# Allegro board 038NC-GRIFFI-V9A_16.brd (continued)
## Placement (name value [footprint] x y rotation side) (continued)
UNK9SH38  SHORT  [DEFAULT_SHORT_SMALL]  120.18 484.64 0 top
UNK9SH39  SHORT  [DEFAULT_SHORT_SMALL]  122.38 484.64 0 top
UNK9SH40  SHORT  [DEFAULT_SHORT_SMALL]  124.58 484.64 0 top
UNK9SH41  SHORT  [DEFAULT_SHORT_SMALL]  126.79 484.64 0 top
UNK9TP_AVSS2/TST  TP01  [TP_040_T]  133.84 274.45 0 top
UNK9TP_GPIO0  TP01  [TP_040_T]  136.57 295.94 90 top
UNK9TP_GPIO1  TP01  [TP_040_T]  136.57 298.48 270 top
UNK9TP_GPIO2  TP01  [TP_040_T]  149.27 295.94 0 top
UNK9TP_GPIO3  TP01  [TP_040_T]  149.27 298.48 270 top
UNK9TP_GPIO4  TP01  [TP_040_T]  146.73 295.94 270 top
UNK9TP_LED0  TP01  [TP_040_T]  144.19 298.48 270 top
UNK9TP_LED1  TP01  [TP_040_T]  144.19 295.94 90 top
UNK9TP_LED2  TP01  [TP_040_T]  146.73 298.48 270 top
UNK9TP_LSIN1_F  TP01  [TP_040_T]  150.99 330.46 0 top
UNK9TP_LSIN1_G  TP01  [TP_040_T]  114.02 486.88 0 top
UNK9TP_LSIN1_S  TP01  [TP_040_T]  148.45 330.46 0 top
UNK9TP_LSIN2/NCHGEN_F  TP01  [TP_040_T]  150.99 335.54 0 top
UNK9TP_LSIN2/NCHGEN_G  TP01  [TP_040_T]  116 486.88 0 top
UNK9TP_LSIN2/NCHGEN_S  TP01  [TP_040_T]  148.45 335.54 0 top
UNK9TP_LSOUT1_F  TP01  [TP_040_T]  139.67 244.47 180 top
UNK9TP_LSOUT1_G  TP01  [TP_040_T]  117.98 486.88 0 top
UNK9TP_LSOUT1_S  TP01  [TP_040_T]  141.65 298.48 270 top
UNK9TP_LSOUT2/SUSPEND1_G  TP01  [TP_040_T]  119.96 486.88 0 top
UNK9TP_LSOUT2/SUSPEND1_S  TP01  [TP_040_T]  141.65 295.94 0 top
UNK9TP_LSOUT2/SUSPEND_F  TP01  [TP_040_T]  158.86 244.47 180 top
UNK9TP_NCHG/ATB0_F  TP01  [TP_040_T]  143.93 292.54 0 top
UNK9TP_NCHG/ATB0_G  TP01  [TP_040_T]  143.93 288.14 0 top
UNK9TP_NCHG/ATB0_S  TP01  [TP_040_T]  147.13 290.34 0 top
UNK9TP_NPG/ATB1_F  TP01  [TP_040_T]  136.47 292.54 0 top
UNK9TP_NPG/ATB1_G  TP01  [TP_040_T]  136.47 288.14 0 top
UNK9TP_NPG/ATB1_S  TP01  [TP_040_T]  139.67 292.54 0 top
UNK9TP_NTC  TP01  [TP_040_T]  151.39 307.08 180 top
UNK9TP_REF_5V  TP01  [TP_040_T]  154.59 242.27 180 top
UNK9TP_SCL  TP01  [TP_040_T]  136.47 330.46 0 top
UNK9TP_SDA  TP01  [TP_040_T]  139.67 330.46 0 top
UNK9TP_SHPHLD_F  TP01  [TP_040_T]  139.11 298.48 270 top
UNK9TP_SHPHLD_S  TP01  [TP_040_T]  139.11 295.94 90 top
UNK9TP_SW_F  TP01  [TP_040_T]  156.07 330.46 0 top
UNK9TP_SW_S  TP01  [TP_040_T]  153.53 330.46 0 top
UNK9TP_VBAT_F  TP01  [TP_040_T]  162.06 287.14 0 top
UNK9TP_VBAT_S  TP01  [TP_040_T]  158.86 287.14 0 top
UNK9TP_VBUS_F  TP01  [TP_040_T]  143.37 330.46 0 top
UNK9TP_VBUS_S  TP01  [TP_040_T]  145.91 330.46 0 top
UNK9TP_VDDIO_F  TP01  [TP_040_T]  158.61 335.54 0 top
UNK9TP_VDDIO_S  TP01  [TP_040_T]  121.95 486.88 0 top
UNK9TP_VEST  TP01  [TP_040_T]  133.28 269.26 0 top
UNK9TP_VOUT_F  TP01  [TP_040_T]  123.93 486.88 0 top
UNK9TP_VOUT_S  TP01  [TP_040_T]  158.61 330.46 0 top
UNK9TP_VSYS_F  TP01  [TP_040_T]  145.91 335.54 0 top
UNK9TP_VSYS_S  TP01  [TP_040_T]  143.37 335.54 0 top
UNK9U1  ADR4550BRZ-SOIC8  [SO8_195X127MM]  156.83 296.98 180 bottom
UNK10C1  1U-6.3-X7R-S6-MU  [C0603]  139.36 142.49 90 bottom
UNK10C2  2.2U-25-X8R-SA-TDK  [C1206]  155.84 178.21 180 bottom
UNK10C3  10U-6.3-X7R-S6-SS  [C0603]  151.92 177.36 270 bottom
UNK10C4  2.2U-25-X8R-SA-TDK  [C1206]  148.38 192.05 180 bottom
UNK10C5  2.2U-25-X8R-SA-TDK  [C1206]  142.68 192.05 0 bottom
UNK10C6  4.7U-6.3-X-S6  [C0603]  161.21 178.21 180 bottom
UNK10C7  0.1U-25-X7R-S6-YA  [C0603]  161.75 238.65 0 bottom
UNK10C8  1U-50-X7R-S6-TY  [C0603]  161.75 237.13 0 bottom
UNK10C9  0.1U-25-X7R-S6-YA  [C0603]  151.9 237.3 270 bottom
UNK10C12  2.2U-25-X8R-SA-TDK  [C1206]  146.98 142.89 90 bottom
UNK10CS1  CNC-S4  [C0402]  142.12 211.3 180 bottom
UNK10CS4  CNC-S4  [C0402]  142.12 207.49 0 bottom
UNK10CS5  CNC-S4  [C0402]  142.12 206.22 0 bottom
UNK10CS19  CNC-S4  [C0402]  155.85 207.02 0 bottom
UNK10CS20  CNC-S4  [C0402]  155.85 208.29 0 bottom
UNK10CS21  CNC-S4  [C0402]  155.85 209.56 0 bottom
UNK10CS22  CNC-S4  [C0402]  153.2 213.05 90 bottom
UNK10CS23  CNC-S4  [C0402]  151.93 213.05 90 bottom
UNK10CS25  CNC-S4  [C0402]  148.12 213.05 90 bottom
UNK10CS26  CNC-S4  [C0402]  146.85 213.05 270 bottom
UNK10CS27  CNC-S4  [C0402]  145.58 213.05 270 bottom
UNK10CS28  CNC-S4  [C0402]  144.31 213.05 90 bottom
UNK10K1  UA2-12NJ-V2  [RL_NECUA2_12V_V2]  152.99 185.33 90 bottom
UNK10K2  UA2-12NJ-V2  [RL_NECUA2_12V_V2]  145.53 185.33 90 bottom
UNK10K3  UA2-12NJ-V2  [RL_NECUA2_12V_V2]  136.66 207.46 270 bottom
UNK10K4  UA2-12NJ-V2  [RL_NECUA2_12V_V2]  145.53 169.7 90 bottom
UNK10K5  UA2-12NJ-V2  [RL_NECUA2_12V_V2]  138.07 169.7 90 bottom
UNK10K6  UA2-12NJ-V2  [RL_NECUA2_12V_V2]  152.99 169.3 270 bottom
UNK10K7  UA2-12NJ-V2  [RL_NECUA2_12V_V2]  160.46 169.7 90 bottom
UNK10K8  UA2-12NJ-V2  [RL_NECUA2_12V_V2]  138.07 185.33 90 bottom
UNK10K9  UA2-12NJ-V2  [RL_NECUA2_12V_V2]  160.46 142.72 270 bottom
UNK10K10  UA2-12NJ-V2  [RL_NECUA2_12V_V2]  160.46 185.33 90 bottom
UNK10K11  UA2-12NJ-V2  [RL_NECUA2_12V_V2]  152.99 229.98 90 bottom
UNK10K12  UA2-12NJ-V2  [RL_NECUA2_12V_V2]  160.46 229.98 90 bottom
UNK10K13  UA2-12NJ-V2  [RL_NECUA2_12V_V2]  138.07 229.58 270 bottom
UNK10K14  UA2-12NJ-V2  [RL_NECUA2_12V_V2]  145.53 229.58 270 bottom
UNK10R1  4.7K-1-S4-WA  [R0402]  136.51 201.49 180 bottom
UNK10R2  3.01K-0.1-S4-PAN  [R0402]  141.8 166.2 90 bottom
UNK10R3  10K-0.1-S4  [R0402]  149.26 172.8 270 bottom
UNK10R7  1K-1-S4  [R0402]  161.78 149.43 0 bottom
UNK10R8  1K-1-S4  [R0402]  159.14 149.43 180 bottom
UNK10R13  0-5-S4  [R0402]  133.39 484.56 0 top
UNK10R14  0-5-S4  [R0402]  135.6 484.56 0 top
UNK10R41  24K-0.1-S4  [R0402]  164.26 166.2 90 bottom
UNK10R42  44.2K-0.1-S4-PAN  [R0402]  164.26 168.4 90 bottom
UNK10RS1  0-5-S4  [R0402]  142.12 208.76 0 bottom
UNK10RS2  NC/0-5-S4  [R0402]  149.39 213.05 270 bottom
UNK10RS3  NC/0-5-S4  [R0402]  142.12 210.03 0 bottom
UNK10RS4  0-5-S4  [R0402]  150.66 213.05 270 bottom
UNK10RS5  0-5-S4  [R0402]  150.02 214.7 0 bottom
UNK10SH2  SHORT  [DEFAULT_SHORT_SMALL]  75.34 475.82 0 top
UNK10SH7  SHORT  [DEFAULT_SHORT_SMALL]  106.18 475.82 0 top
UNK10SH9  SHORT  [DEFAULT_SHORT_SMALL]  108.39 475.82 0 top
UNK10SH14  SHORT  [DEFAULT_SHORT_SMALL]  70.93 475.82 0 top
UNK10SH16  SHORT  [DEFAULT_SHORT_SMALL]  73.14 475.82 0 top
UNK10SH20  SHORT  [DEFAULT_SHORT_SMALL]  77.54 475.82 0 top
UNK10SH29  SHORT  [DEFAULT_SHORT_SMALL]  79.75 475.82 0 top
UNK10SH30  SHORT  [DEFAULT_SHORT_SMALL]  81.95 475.82 0 top
UNK10SH32  SHORT  [DEFAULT_SHORT_SMALL]  84.15 475.82 0 top
UNK10SH33  SHORT  [DEFAULT_SHORT_SMALL]  86.36 475.82 0 top
UNK10SH34  SHORT  [DEFAULT_SHORT_SMALL]  88.56 475.82 0 top
UNK10SH35  SHORT  [DEFAULT_SHORT_SMALL]  90.76 475.82 0 top
UNK10SH36  SHORT  [DEFAULT_SHORT_SMALL]  92.97 475.82 0 top
UNK10SH37  SHORT  [DEFAULT_SHORT_SMALL]  95.17 475.82 0 top
UNK10SH38  SHORT  [DEFAULT_SHORT_SMALL]  97.37 475.82 0 top
UNK10SH39  SHORT  [DEFAULT_SHORT_SMALL]  99.58 475.82 0 top
UNK10SH40  SHORT  [DEFAULT_SHORT_SMALL]  101.78 475.82 0 top
UNK10SH41  SHORT  [DEFAULT_SHORT_SMALL]  103.98 475.82 0 top
UNK10TP_AVSS2/TST  TP01  [TP_040_T]  133.84 214.45 0 top
UNK10TP_GPIO0  TP01  [TP_040_T]  149.17 178.59 270 top
UNK10TP_GPIO1  TP01  [TP_040_T]  149.17 176.05 90 top
UNK10TP_GPIO2  TP01  [TP_040_T]  136.47 178.59 180 top
UNK10TP_GPIO3  TP01  [TP_040_T]  136.47 176.05 90 top
UNK10TP_GPIO4  TP01  [TP_040_T]  139.01 178.59 90 top
UNK10TP_LED0  TP01  [TP_040_T]  141.55 176.05 90 top
UNK10TP_LED1  TP01  [TP_040_T]  141.55 178.59 270 top
UNK10TP_LED2  TP01  [TP_040_T]  139.01 176.05 90 top
UNK10TP_LSIN1_F  TP01  [TP_040_T]  146.98 146.72 180 top
UNK10TP_LSIN1_G  TP01  [TP_040_T]  197.79 484.9 0 top
UNK10TP_LSIN1_S  TP01  [TP_040_T]  149.52 146.72 180 top
UNK10TP_LSIN2/NCHGEN_F  TP01  [TP_040_T]  146.98 141.64 180 top
UNK10TP_LSIN2/NCHGEN_G  TP01  [TP_040_T]  199.77 484.9 0 top
UNK10TP_LSIN2/NCHGEN_S  TP01  [TP_040_T]  149.52 141.64 180 top
UNK10TP_LSOUT1_F  TP01  [TP_040_T]  201.75 484.9 0 top
UNK10TP_LSOUT1_G  TP01  [TP_040_T]  203.73 484.9 0 top
UNK10TP_LSOUT1_S  TP01  [TP_040_T]  144.09 176.05 90 top
UNK10TP_LSOUT2/SUSPEND1_G  TP01  [TP_040_T]  205.71 484.9 0 top
UNK10TP_LSOUT2/SUSPEND1_S  TP01  [TP_040_T]  144.09 178.59 180 top
UNK10TP_LSOUT2/SUSPEND_F  TP01  [TP_040_T]  207.69 484.9 0 top
UNK10TP_NCHG/ATB0_F  TP01  [TP_040_T]  143.93 233.58 0 top
UNK10TP_NCHG/ATB0_G  TP01  [TP_040_T]  143.93 229.18 0 top
UNK10TP_NCHG/ATB0_S  TP01  [TP_040_T]  147.13 231.38 0 top
UNK10TP_NPG/ATB1_F  TP01  [TP_040_T]  136.47 233.58 0 top
UNK10TP_NPG/ATB1_G  TP01  [TP_040_T]  136.47 229.18 0 top
UNK10TP_NPG/ATB1_S  TP01  [TP_040_T]  139.67 233.58 0 top
UNK10TP_NTC  TP01  [TP_040_T]  147.13 167.9 0 top
UNK10TP_REF_5V  TP01  [TP_040_T]  209.67 484.9 0 top
UNK10TP_SCL  TP01  [TP_040_T]  162.06 144.52 180 top
UNK10TP_SDA  TP01  [TP_040_T]  158.86 144.52 180 top
UNK10TP_SHPHLD_F  TP01  [TP_040_T]  146.63 176.05 90 top
UNK10TP_SHPHLD_S  TP01  [TP_040_T]  146.63 178.59 270 top
UNK10TP_SW_F  TP01  [TP_040_T]  141.9 146.72 180 top
UNK10TP_SW_S  TP01  [TP_040_T]  144.44 146.72 180 top
UNK10TP_VBAT_F  TP01  [TP_040_T]  162.06 228.18 0 top
UNK10TP_VBAT_S  TP01  [TP_040_T]  158.86 228.18 0 top
UNK10TP_VBUS_F  TP01  [TP_040_T]  154.6 146.72 180 top
UNK10TP_VBUS_S  TP01  [TP_040_T]  152.06 146.72 180 top
UNK10TP_VDDIO_F  TP01  [TP_040_T]  139.36 141.64 180 top
UNK10TP_VDDIO_S  TP01  [TP_040_T]  136.82 141.64 180 top
UNK10TP_VEST  TP01  [TP_040_T]  133.28 209.26 0 top
UNK10TP_VOUT_F  TP01  [TP_040_T]  136.82 146.72 180 top
UNK10TP_VOUT_S  TP01  [TP_040_T]  139.36 146.72 180 top
UNK10TP_VSYS_F  TP01  [TP_040_T]  152.06 141.64 180 top
UNK10TP_VSYS_S  TP01  [TP_040_T]  154.6 141.64 180 top
UNK10U1  ADR4550BRZ-SOIC8  [SO8_195X127MM]  156.32 238.02 180 bottom
UNK11C1  1U-6.3-X7R-S6-MU  [C0603]  188.61 334.69 270 bottom
UNK11C2  2.2U-25-X8R-SA-TDK  [C1206]  179.52 237.92 90 bottom
UNK11C3  10U-6.3-X7R-S6-SS  [C0603]  177.13 238.61 270 bottom
UNK11C4  2.2U-25-X8R-SA-TDK  [C1206]  169.67 237.92 90 bottom
UNK11C5  2.2U-25-X8R-SA-TDK  [C1206]  166.47 237.92 270 bottom
UNK11C6  4.7U-6.3-X-S6  [C0603]  194.26 241.42 270 bottom
UNK11C7  0.1U-25-X7R-S6-YA  [C0603]  192.25 297.61 0 bottom
UNK11C8  1U-50-X7R-S6-TY  [C0603]  192.25 296.09 0 bottom
UNK11C9  0.1U-25-X7R-S6-YA  [C0603]  182.41 296.26 270 bottom
UNK11C12  2.2U-25-X8R-SA-TDK  [C1206]  180.99 334.29 270 bottom
UNK11CS1  CNC-S4  [C0402]  172.12 271.3 180 bottom
UNK11CS4  CNC-S4  [C0402]  172.12 267.49 0 bottom
UNK11CS5  CNC-S4  [C0402]  172.12 266.22 0 bottom
UNK11CS19  CNC-S4  [C0402]  185.85 267.02 0 bottom
UNK11CS20  CNC-S4  [C0402]  185.85 268.29 0 bottom
UNK11CS21  CNC-S4  [C0402]  185.85 269.56 0 bottom
UNK11CS22  CNC-S4  [C0402]  183.19 273.05 90 bottom
UNK11CS23  CNC-S4  [C0402]  181.92 273.05 90 bottom
UNK11CS25  CNC-S4  [C0402]  178.11 273.05 90 bottom
UNK11CS26  CNC-S4  [C0402]  176.84 273.05 270 bottom
UNK11CS27  CNC-S4  [C0402]  175.57 273.05 270 bottom
UNK11CS28  CNC-S4  [C0402]  174.3 273.05 90 bottom
UNK11K1  UA2-12NJ-V2  [RL_NECUA2_12V_V2]  182.99 246.27 90 bottom
UNK11K2  UA2-12NJ-V2  [RL_NECUA2_12V_V2]  175.53 246.27 90 bottom
UNK11K3  UA2-12NJ-V2  [RL_NECUA2_12V_V2]  166.66 267.46 270 bottom
UNK11K4  UA2-12NJ-V2  [RL_NECUA2_12V_V2]  182.99 305.28 270 bottom
UNK11K5  UA2-12NJ-V2  [RL_NECUA2_12V_V2]  190.46 305.28 270 bottom
UNK11K6  UA2-12NJ-V2  [RL_NECUA2_12V_V2]  175.53 305.68 90 bottom
UNK11K7  UA2-12NJ-V2  [RL_NECUA2_12V_V2]  168.07 305.28 270 bottom
UNK11K8  UA2-12NJ-V2  [RL_NECUA2_12V_V2]  168.07 246.27 90 bottom
UNK11K9  UA2-12NJ-V2  [RL_NECUA2_12V_V2]  168.07 332.26 90 bottom
UNK11K10  UA2-12NJ-V2  [RL_NECUA2_12V_V2]  182.99 288.94 90 bottom
UNK11K11  UA2-12NJ-V2  [RL_NECUA2_12V_V2]  190.46 246.27 90 bottom
UNK11K12  UA2-12NJ-V2  [RL_NECUA2_12V_V2]  190.46 288.94 90 bottom
UNK11K13  UA2-12NJ-V2  [RL_NECUA2_12V_V2]  168.07 288.54 270 bottom
UNK11K14  UA2-12NJ-V2  [RL_NECUA2_12V_V2]  175.53 288.54 270 bottom
UNK11R1  4.7K-1-S4-WA  [R0402]  166.51 261.49 180 bottom
UNK11R2  3.01K-0.1-S4-PAN  [R0402]  186.73 308.78 270 bottom
UNK11R3  10K-0.1-S4  [R0402]  179.26 301.18 270 bottom
UNK11R7  1K-1-S4  [R0402]  166.75 325.55 180 bottom
UNK11R8  1K-1-S4  [R0402]  169.39 325.55 0 bottom
UNK11R13  0-5-S4  [R0402]  137.8 484.56 0 top
UNK11R14  0-5-S4  [R0402]  140 484.56 0 top
UNK11R41  24K-0.1-S4  [R0402]  164.26 308.78 270 bottom
UNK11R42  44.2K-0.1-S4-PAN  [R0402]  164.26 306.58 270 bottom
UNK11RS1  0-5-S4  [R0402]  172.12 268.76 0 bottom
UNK11RS2  NC/0-5-S4  [R0402]  179.38 273.05 270 bottom
UNK11RS3  NC/0-5-S4  [R0402]  172.12 270.03 0 bottom
UNK11RS4  0-5-S4  [R0402]  180.65 273.05 270 bottom
UNK11RS5  0-5-S4  [R0402]  180.02 274.7 0 bottom
UNK11SH2  SHORT  [DEFAULT_SHORT_SMALL]  115 475.82 0 top
UNK11SH7  SHORT  [DEFAULT_SHORT_SMALL]  145.84 475.82 0 top
UNK11SH9  SHORT  [DEFAULT_SHORT_SMALL]  148.05 475.82 0 top
UNK11SH14  SHORT  [DEFAULT_SHORT_SMALL]  110.59 475.82 0 top
UNK11SH16  SHORT  [DEFAULT_SHORT_SMALL]  112.79 475.82 0 top
UNK11SH20  SHORT  [DEFAULT_SHORT_SMALL]  117.2 475.82 0 top
UNK11SH29  SHORT  [DEFAULT_SHORT_SMALL]  119.4 475.82 0 top
UNK11SH30  SHORT  [DEFAULT_SHORT_SMALL]  121.61 475.82 0 top
UNK11SH32  SHORT  [DEFAULT_SHORT_SMALL]  123.81 475.82 0 top
UNK11SH33  SHORT  [DEFAULT_SHORT_SMALL]  126.01 475.82 0 top
UNK11SH34  SHORT  [DEFAULT_SHORT_SMALL]  128.22 475.82 0 top
UNK11SH35  SHORT  [DEFAULT_SHORT_SMALL]  130.42 475.82 0 top
UNK11SH36  SHORT  [DEFAULT_SHORT_SMALL]  132.62 475.82 0 top
UNK11SH37  SHORT  [DEFAULT_SHORT_SMALL]  134.83 475.82 0 top
UNK11SH38  SHORT  [DEFAULT_SHORT_SMALL]  137.03 475.82 0 top
UNK11SH39  SHORT  [DEFAULT_SHORT_SMALL]  139.23 475.82 0 top
UNK11SH40  SHORT  [DEFAULT_SHORT_SMALL]  141.44 475.82 0 top
UNK11SH41  SHORT  [DEFAULT_SHORT_SMALL]  143.64 475.82 0 top
UNK11TP_AVSS2/TST  TP01  [TP_040_T]  163.84 274.45 0 top
UNK11TP_GPIO0  TP01  [TP_040_T]  166.57 295.94 90 top
UNK11TP_GPIO1  TP01  [TP_040_T]  166.57 298.48 270 top
UNK11TP_GPIO2  TP01  [TP_040_T]  179.27 295.94 0 top
UNK11TP_GPIO3  TP01  [TP_040_T]  179.27 298.48 270 top
UNK11TP_GPIO4  TP01  [TP_040_T]  176.73 295.94 270 top
UNK11TP_LED0  TP01  [TP_040_T]  174.19 298.48 270 top
UNK11TP_LED1  TP01  [TP_040_T]  174.19 295.94 90 top
UNK11TP_LED2  TP01  [TP_040_T]  176.73 298.48 270 top
UNK11TP_LSIN1_F  TP01  [TP_040_T]  180.99 330.46 0 top
UNK11TP_LSIN1_G  TP01  [TP_040_T]  211.65 484.9 0 top
UNK11TP_LSIN1_S  TP01  [TP_040_T]  178.45 330.46 0 top
UNK11TP_LSIN2/NCHGEN_F  TP01  [TP_040_T]  180.99 335.54 0 top
UNK11TP_LSIN2/NCHGEN_G  TP01  [TP_040_T]  213.64 484.9 0 top
UNK11TP_LSIN2/NCHGEN_S  TP01  [TP_040_T]  178.45 335.54 0 top
UNK11TP_LSOUT1_F  TP01  [TP_040_T]  169.67 244.47 180 top
UNK11TP_LSOUT1_G  TP01  [TP_040_T]  215.62 484.9 0 top
UNK11TP_LSOUT1_S  TP01  [TP_040_T]  171.65 298.48 270 top
UNK11TP_LSOUT2/SUSPEND1_G  TP01  [TP_040_T]  217.6 484.9 0 top
UNK11TP_LSOUT2/SUSPEND1_S  TP01  [TP_040_T]  171.65 295.94 0 top
UNK11TP_LSOUT2/SUSPEND_F  TP01  [TP_040_T]  188.86 244.47 180 top
UNK11TP_NCHG/ATB0_F  TP01  [TP_040_T]  173.93 292.54 0 top
UNK11TP_NCHG/ATB0_G  TP01  [TP_040_T]  173.93 288.14 0 top
UNK11TP_NCHG/ATB0_S  TP01  [TP_040_T]  177.13 290.34 0 top
UNK11TP_NPG/ATB1_F  TP01  [TP_040_T]  166.47 292.54 0 top
UNK11TP_NPG/ATB1_G  TP01  [TP_040_T]  166.47 288.14 0 top
UNK11TP_NPG/ATB1_S  TP01  [TP_040_T]  169.67 292.54 0 top
UNK11TP_NTC  TP01  [TP_040_T]  181.39 307.08 180 top
UNK11TP_REF_5V  TP01  [TP_040_T]  184.59 242.27 180 top
UNK11TP_SCL  TP01  [TP_040_T]  166.47 330.46 0 top
UNK11TP_SDA  TP01  [TP_040_T]  169.67 330.46 0 top
UNK11TP_SHPHLD_F  TP01  [TP_040_T]  169.11 298.48 270 top
UNK11TP_SHPHLD_S  TP01  [TP_040_T]  169.11 295.94 90 top
UNK11TP_SW_F  TP01  [TP_040_T]  186.07 330.46 0 top
UNK11TP_SW_S  TP01  [TP_040_T]  183.53 330.46 0 top
UNK11TP_VBAT_F  TP01  [TP_040_T]  192.06 287.14 0 top
UNK11TP_VBAT_S  TP01  [TP_040_T]  188.86 287.14 0 top
UNK11TP_VBUS_F  TP01  [TP_040_T]  173.37 330.46 0 top
UNK11TP_VBUS_S  TP01  [TP_040_T]  175.91 330.46 0 top
UNK11TP_VDDIO_F  TP01  [TP_040_T]  188.61 335.54 0 top
UNK11TP_VDDIO_S  TP01  [TP_040_T]  219.58 484.9 0 top
UNK11TP_VEST  TP01  [TP_040_T]  163.28 269.26 0 top
UNK11TP_VOUT_F  TP01  [TP_040_T]  221.56 484.9 0 top
UNK11TP_VOUT_S  TP01  [TP_040_T]  188.61 330.46 0 top
UNK11TP_VSYS_F  TP01  [TP_040_T]  175.91 335.54 0 top
UNK11TP_VSYS_S  TP01  [TP_040_T]  173.37 335.54 0 top
UNK11U1  ADR4550BRZ-SOIC8  [SO8_195X127MM]  186.83 296.98 180 bottom
UNK12C1  1U-6.3-X7R-S6-MU  [C0603]  169.36 142.49 90 bottom
UNK12C2  2.2U-25-X8R-SA-TDK  [C1206]  185.84 178.21 180 bottom
UNK12C3  10U-6.3-X7R-S6-SS  [C0603]  181.92 177.36 270 bottom
UNK12C4  2.2U-25-X8R-SA-TDK  [C1206]  178.38 192.05 180 bottom
UNK12C5  2.2U-25-X8R-SA-TDK  [C1206]  172.68 192.05 0 bottom
UNK12C6  4.7U-6.3-X-S6  [C0603]  191.21 178.21 180 bottom
UNK12C7  0.1U-25-X7R-S6-YA  [C0603]  191.75 238.65 0 bottom
UNK12C8  1U-50-X7R-S6-TY  [C0603]  191.75 237.13 0 bottom
UNK12C9  0.1U-25-X7R-S6-YA  [C0603]  181.9 237.3 270 bottom
UNK12C12  2.2U-25-X8R-SA-TDK  [C1206]  176.98 142.89 90 bottom
UNK12CS1  CNC-S4  [C0402]  172.12 211.3 180 bottom
UNK12CS4  CNC-S4  [C0402]  172.12 207.49 0 bottom
UNK12CS5  CNC-S4  [C0402]  172.12 206.22 0 bottom
UNK12CS19  CNC-S4  [C0402]  185.85 207.02 0 bottom
UNK12CS20  CNC-S4  [C0402]  185.85 208.29 0 bottom
UNK12CS21  CNC-S4  [C0402]  185.85 209.56 0 bottom
UNK12CS22  CNC-S4  [C0402]  183.19 213.05 90 bottom
UNK12CS23  CNC-S4  [C0402]  181.92 213.05 90 bottom
UNK12CS25  CNC-S4  [C0402]  178.11 213.05 90 bottom
UNK12CS26  CNC-S4  [C0402]  176.84 213.05 270 bottom
UNK12CS27  CNC-S4  [C0402]  175.57 213.05 270 bottom
UNK12CS28  CNC-S4  [C0402]  174.3 213.05 90 bottom
UNK12K1  UA2-12NJ-V2  [RL_NECUA2_12V_V2]  182.99 185.33 90 bottom
UNK12K2  UA2-12NJ-V2  [RL_NECUA2_12V_V2]  175.53 185.33 90 bottom
UNK12K3  UA2-12NJ-V2  [RL_NECUA2_12V_V2]  166.66 207.46 270 bottom
UNK12K4  UA2-12NJ-V2  [RL_NECUA2_12V_V2]  175.53 169.7 90 bottom
UNK12K5  UA2-12NJ-V2  [RL_NECUA2_12V_V2]  168.07 169.7 90 bottom
UNK12K6  UA2-12NJ-V2  [RL_NECUA2_12V_V2]  182.99 169.3 270 bottom
UNK12K7  UA2-12NJ-V2  [RL_NECUA2_12V_V2]  190.46 169.7 90 bottom
UNK12K8  UA2-12NJ-V2  [RL_NECUA2_12V_V2]  168.07 185.33 90 bottom
UNK12K9  UA2-12NJ-V2  [RL_NECUA2_12V_V2]  190.46 142.72 270 bottom
UNK12K10  UA2-12NJ-V2  [RL_NECUA2_12V_V2]  190.46 185.33 90 bottom
UNK12K11  UA2-12NJ-V2  [RL_NECUA2_12V_V2]  182.99 229.98 90 bottom
UNK12K12  UA2-12NJ-V2  [RL_NECUA2_12V_V2]  190.46 229.98 90 bottom
UNK12K13  UA2-12NJ-V2  [RL_NECUA2_12V_V2]  168.07 229.58 270 bottom
UNK12K14  UA2-12NJ-V2  [RL_NECUA2_12V_V2]  175.53 229.58 270 bottom
UNK12R1  4.7K-1-S4-WA  [R0402]  166.51 201.49 180 bottom
UNK12R2  3.01K-0.1-S4-PAN  [R0402]  171.8 166.2 90 bottom
UNK12R3  10K-0.1-S4  [R0402]  179.26 172.8 270 bottom
UNK12R7  1K-1-S4  [R0402]  191.78 149.43 0 bottom
UNK12R8  1K-1-S4  [R0402]  189.14 149.43 180 bottom
UNK12R13  0-5-S4  [R0402]  142.21 484.56 0 top
UNK12R14  0-5-S4  [R0402]  144.41 484.56 0 top
UNK12R41  24K-0.1-S4  [R0402]  194.26 166.2 90 bottom
UNK12R42  44.2K-0.1-S4-PAN  [R0402]  194.26 168.4 90 bottom
UNK12RS1  0-5-S4  [R0402]  172.12 208.76 0 bottom
UNK12RS2  NC/0-5-S4  [R0402]  179.38 213.05 270 bottom
UNK12RS3  NC/0-5-S4  [R0402]  172.12 210.03 0 bottom
UNK12RS4  0-5-S4  [R0402]  180.65 213.05 270 bottom
UNK12RS5  0-5-S4  [R0402]  180.02 214.7 0 bottom
UNK12SH2  SHORT  [DEFAULT_SHORT_SMALL]  154.66 475.82 0 top
UNK12SH7  SHORT  [DEFAULT_SHORT_SMALL]  185.5 475.82 0 top
UNK12SH9  SHORT  [DEFAULT_SHORT_SMALL]  187.7 475.82 0 top
UNK12SH14  SHORT  [DEFAULT_SHORT_SMALL]  150.25 475.82 0 top
UNK12SH16  SHORT  [DEFAULT_SHORT_SMALL]  152.45 475.82 0 top
UNK12SH20  SHORT  [DEFAULT_SHORT_SMALL]  156.86 475.82 0 top
UNK12SH29  SHORT  [DEFAULT_SHORT_SMALL]  159.06 475.82 0 top
UNK12SH30  SHORT  [DEFAULT_SHORT_SMALL]  161.26 475.82 0 top
UNK12SH32  SHORT  [DEFAULT_SHORT_SMALL]  163.47 475.82 0 top
UNK12SH33  SHORT  [DEFAULT_SHORT_SMALL]  165.67 475.82 0 top
UNK12SH34  SHORT  [DEFAULT_SHORT_SMALL]  167.87 475.82 0 top
UNK12SH35  SHORT  [DEFAULT_SHORT_SMALL]  170.08 475.82 0 top
UNK12SH36  SHORT  [DEFAULT_SHORT_SMALL]  172.28 475.82 0 top
UNK12SH37  SHORT  [DEFAULT_SHORT_SMALL]  174.48 475.82 0 top
UNK12SH38  SHORT  [DEFAULT_SHORT_SMALL]  176.69 475.82 0 top
UNK12SH39  SHORT  [DEFAULT_SHORT_SMALL]  178.89 475.82 0 top
UNK12SH40  SHORT  [DEFAULT_SHORT_SMALL]  181.09 475.82 0 top
UNK12SH41  SHORT  [DEFAULT_SHORT_SMALL]  183.3 475.82 0 top
UNK12TP_AVSS2/TST  TP01  [TP_040_T]  163.84 214.45 0 top
UNK12TP_GPIO0  TP01  [TP_040_T]  179.17 178.59 270 top
UNK12TP_GPIO1  TP01  [TP_040_T]  179.17 176.05 90 top
UNK12TP_GPIO2  TP01  [TP_040_T]  166.47 178.59 180 top
UNK12TP_GPIO3  TP01  [TP_040_T]  166.47 176.05 90 top
UNK12TP_GPIO4  TP01  [TP_040_T]  169.01 178.59 90 top
UNK12TP_LED0  TP01  [TP_040_T]  171.55 176.05 90 top
UNK12TP_LED1  TP01  [TP_040_T]  171.55 178.59 270 top
UNK12TP_LED2  TP01  [TP_040_T]  169.01 176.05 90 top
UNK12TP_LSIN1_F  TP01  [TP_040_T]  176.98 146.72 180 top
UNK12TP_LSIN1_G  TP01  [TP_040_T]  223.54 484.9 0 top
UNK12TP_LSIN1_S  TP01  [TP_040_T]  179.52 146.72 180 top
UNK12TP_LSIN2/NCHGEN_F  TP01  [TP_040_T]  176.98 141.64 180 top
UNK12TP_LSIN2/NCHGEN_G  TP01  [TP_040_T]  225.52 484.9 0 top
UNK12TP_LSIN2/NCHGEN_S  TP01  [TP_040_T]  179.52 141.64 180 top
UNK12TP_LSOUT1_F  TP01  [TP_040_T]  227.5 484.9 0 top
UNK12TP_LSOUT1_G  TP01  [TP_040_T]  229.49 484.9 0 top
UNK12TP_LSOUT1_S  TP01  [TP_040_T]  174.09 176.05 90 top
UNK12TP_LSOUT2/SUSPEND1_G  TP01  [TP_040_T]  231.47 484.9 0 top
UNK12TP_LSOUT2/SUSPEND1_S  TP01  [TP_040_T]  174.09 178.59 180 top
UNK12TP_LSOUT2/SUSPEND_F  TP01  [TP_040_T]  233.45 484.9 0 top
UNK12TP_NCHG/ATB0_F  TP01  [TP_040_T]  173.93 233.58 0 top
UNK12TP_NCHG/ATB0_G  TP01  [TP_040_T]  173.93 229.18 0 top
UNK12TP_NCHG/ATB0_S  TP01  [TP_040_T]  177.13 231.38 0 top
UNK12TP_NPG/ATB1_F  TP01  [TP_040_T]  166.47 233.58 0 top
UNK12TP_NPG/ATB1_G  TP01  [TP_040_T]  166.47 229.18 0 top
UNK12TP_NPG/ATB1_S  TP01  [TP_040_T]  169.67 233.58 0 top
UNK12TP_NTC  TP01  [TP_040_T]  177.13 167.9 0 top
UNK12TP_REF_5V  TP01  [TP_040_T]  235.43 484.9 0 top
UNK12TP_SCL  TP01  [TP_040_T]  192.06 144.52 180 top
UNK12TP_SDA  TP01  [TP_040_T]  188.86 144.52 180 top
UNK12TP_SHPHLD_F  TP01  [TP_040_T]  176.63 176.05 90 top
UNK12TP_SHPHLD_S  TP01  [TP_040_T]  176.63 178.59 270 top
UNK12TP_SW_F  TP01  [TP_040_T]  171.9 146.72 180 top
UNK12TP_SW_S  TP01  [TP_040_T]  174.44 146.72 180 top
UNK12TP_VBAT_F  TP01  [TP_040_T]  192.06 228.18 0 top
UNK12TP_VBAT_S  TP01  [TP_040_T]  188.86 228.18 0 top
UNK12TP_VBUS_F  TP01  [TP_040_T]  184.6 146.72 180 top
UNK12TP_VBUS_S  TP01  [TP_040_T]  182.06 146.72 180 top
UNK12TP_VDDIO_F  TP01  [TP_040_T]  169.36 141.64 180 top
UNK12TP_VDDIO_S  TP01  [TP_040_T]  166.82 141.64 180 top
UNK12TP_VEST  TP01  [TP_040_T]  163.28 209.26 0 top
UNK12TP_VOUT_F  TP01  [TP_040_T]  166.82 146.72 180 top
UNK12TP_VOUT_S  TP01  [TP_040_T]  169.36 146.72 180 top
UNK12TP_VSYS_F  TP01  [TP_040_T]  182.06 141.64 180 top
UNK12TP_VSYS_S  TP01  [TP_040_T]  184.6 141.64 180 top
UNK12U1  ADR4550BRZ-SOIC8  [SO8_195X127MM]  186.32 238.02 180 bottom
UNK13C1  1U-6.3-X7R-S6-MU  [C0603]  218.61 334.69 270 bottom
UNK13C2  2.2U-25-X8R-SA-TDK  [C1206]  209.52 237.92 90 bottom
UNK13C3  10U-6.3-X7R-S6-SS  [C0603]  207.13 238.61 270 bottom
UNK13C4  2.2U-25-X8R-SA-TDK  [C1206]  199.67 237.92 90 bottom
UNK13C5  2.2U-25-X8R-SA-TDK  [C1206]  196.47 237.92 270 bottom
UNK13C6  4.7U-6.3-X-S6  [C0603]  224.26 241.42 270 bottom
UNK13C7  0.1U-25-X7R-S6-YA  [C0603]  222.25 297.61 0 bottom
UNK13C8  1U-50-X7R-S6-TY  [C0603]  222.25 296.09 0 bottom
UNK13C9  0.1U-25-X7R-S6-YA  [C0603]  212.41 296.26 270 bottom
UNK13C12  2.2U-25-X8R-SA-TDK  [C1206]  210.99 334.29 270 bottom
UNK13CS1  CNC-S4  [C0402]  202.12 271.3 180 bottom
UNK13CS4  CNC-S4  [C0402]  202.12 267.49 0 bottom
UNK13CS5  CNC-S4  [C0402]  202.12 266.22 0 bottom
UNK13CS19  CNC-S4  [C0402]  215.85 267.02 0 bottom
UNK13CS20  CNC-S4  [C0402]  215.85 268.29 0 bottom
UNK13CS21  CNC-S4  [C0402]  215.85 269.56 0 bottom
UNK13CS22  CNC-S4  [C0402]  213.19 273.05 90 bottom
UNK13CS23  CNC-S4  [C0402]  211.92 273.05 90 bottom
UNK13CS25  CNC-S4  [C0402]  208.11 273.05 90 bottom
UNK13CS26  CNC-S4  [C0402]  206.84 273.05 270 bottom
UNK13CS27  CNC-S4  [C0402]  205.57 273.05 270 bottom
UNK13CS28  CNC-S4  [C0402]  204.3 273.05 90 bottom
UNK13K1  UA2-12NJ-V2  [RL_NECUA2_12V_V2]  212.99 246.27 90 bottom
UNK13K2  UA2-12NJ-V2  [RL_NECUA2_12V_V2]  205.53 246.27 90 bottom
UNK13K3  UA2-12NJ-V2  [RL_NECUA2_12V_V2]  196.66 267.46 270 bottom
UNK13K4  UA2-12NJ-V2  [RL_NECUA2_12V_V2]  212.99 305.28 270 bottom
UNK13K5  UA2-12NJ-V2  [RL_NECUA2_12V_V2]  220.46 305.28 270 bottom
UNK13K6  UA2-12NJ-V2  [RL_NECUA2_12V_V2]  205.53 305.68 90 bottom
UNK13K7  UA2-12NJ-V2  [RL_NECUA2_12V_V2]  198.07 305.28 270 bottom
UNK13K8  UA2-12NJ-V2  [RL_NECUA2_12V_V2]  198.07 246.27 90 bottom
UNK13K9  UA2-12NJ-V2  [RL_NECUA2_12V_V2]  198.07 332.26 90 bottom
UNK13K10  UA2-12NJ-V2  [RL_NECUA2_12V_V2]  212.99 288.94 90 bottom
UNK13K11  UA2-12NJ-V2  [RL_NECUA2_12V_V2]  220.46 246.27 90 bottom
UNK13K12  UA2-12NJ-V2  [RL_NECUA2_12V_V2]  220.46 288.94 90 bottom
UNK13K13  UA2-12NJ-V2  [RL_NECUA2_12V_V2]  198.07 288.54 270 bottom
UNK13K14  UA2-12NJ-V2  [RL_NECUA2_12V_V2]  205.53 288.54 270 bottom
UNK13R1  4.7K-1-S4-WA  [R0402]  196.51 261.49 180 bottom
UNK13R2  3.01K-0.1-S4-PAN  [R0402]  216.73 308.78 270 bottom
UNK13R3  10K-0.1-S4  [R0402]  209.26 301.18 270 bottom
UNK13R7  1K-1-S4  [R0402]  196.75 325.55 180 bottom
UNK13R8  1K-1-S4  [R0402]  199.39 325.55 0 bottom
UNK13R13  0-5-S4  [R0402]  146.61 484.56 0 top
UNK13R14  0-5-S4  [R0402]  148.82 484.56 0 top
UNK13R41  24K-0.1-S4  [R0402]  194.26 308.78 270 bottom
UNK13R42  44.2K-0.1-S4-PAN  [R0402]  194.26 306.58 270 bottom
UNK13RS1  0-5-S4  [R0402]  202.12 268.76 0 bottom
UNK13RS2  NC/0-5-S4  [R0402]  209.38 273.05 270 bottom
UNK13RS3  NC/0-5-S4  [R0402]  202.12 270.03 0 bottom
UNK13RS4  0-5-S4  [R0402]  210.65 273.05 270 bottom
UNK13RS5  0-5-S4  [R0402]  210.02 274.7 0 bottom
UNK13SH2  SHORT  [DEFAULT_SHORT_SMALL]  194.31 475.82 0 top
UNK13SH7  SHORT  [DEFAULT_SHORT_SMALL]  225.16 475.82 0 top
UNK13SH9  SHORT  [DEFAULT_SHORT_SMALL]  227.36 475.82 0 top
UNK13SH14  SHORT  [DEFAULT_SHORT_SMALL]  189.91 475.82 0 top
UNK13SH16  SHORT  [DEFAULT_SHORT_SMALL]  192.11 475.82 0 top
UNK13SH20  SHORT  [DEFAULT_SHORT_SMALL]  196.52 475.82 0 top
UNK13SH29  SHORT  [DEFAULT_SHORT_SMALL]  198.72 475.82 0 top
UNK13SH30  SHORT  [DEFAULT_SHORT_SMALL]  200.92 475.82 0 top
UNK13SH32  SHORT  [DEFAULT_SHORT_SMALL]  203.13 475.82 0 top
UNK13SH33  SHORT  [DEFAULT_SHORT_SMALL]  205.33 475.82 0 top
UNK13SH34  SHORT  [DEFAULT_SHORT_SMALL]  207.53 475.82 0 top
UNK13SH35  SHORT  [DEFAULT_SHORT_SMALL]  209.74 475.82 0 top
UNK13SH36  SHORT  [DEFAULT_SHORT_SMALL]  211.94 475.82 0 top
UNK13SH37  SHORT  [DEFAULT_SHORT_SMALL]  214.14 475.82 0 top
UNK13SH38  SHORT  [DEFAULT_SHORT_SMALL]  216.34 475.82 0 top
UNK13SH39  SHORT  [DEFAULT_SHORT_SMALL]  218.55 475.82 0 top
UNK13SH40  SHORT  [DEFAULT_SHORT_SMALL]  220.75 475.82 0 top
UNK13SH41  SHORT  [DEFAULT_SHORT_SMALL]  222.95 475.82 0 top
UNK13TP_AVSS2/TST  TP01  [TP_040_T]  193.84 274.45 0 top
UNK13TP_GPIO0  TP01  [TP_040_T]  196.57 295.94 90 top
UNK13TP_GPIO1  TP01  [TP_040_T]  196.57 298.48 270 top
UNK13TP_GPIO2  TP01  [TP_040_T]  209.27 295.94 0 top
UNK13TP_GPIO3  TP01  [TP_040_T]  209.27 298.48 270 top
UNK13TP_GPIO4  TP01  [TP_040_T]  206.73 295.94 270 top
UNK13TP_LED0  TP01  [TP_040_T]  204.19 298.48 270 top
UNK13TP_LED1  TP01  [TP_040_T]  204.19 295.94 90 top
UNK13TP_LED2  TP01  [TP_040_T]  206.73 298.48 270 top
UNK13TP_LSIN1_F  TP01  [TP_040_T]  210.99 330.46 0 top
UNK13TP_LSIN1_G  TP01  [TP_040_T]  237.41 484.9 0 top
UNK13TP_LSIN1_S  TP01  [TP_040_T]  208.45 330.46 0 top
UNK13TP_LSIN2/NCHGEN_F  TP01  [TP_040_T]  210.99 335.54 0 top
UNK13TP_LSIN2/NCHGEN_G  TP01  [TP_040_T]  239.39 484.9 0 top
UNK13TP_LSIN2/NCHGEN_S  TP01  [TP_040_T]  208.45 335.54 0 top
UNK13TP_LSOUT1_F  TP01  [TP_040_T]  199.67 244.47 180 top
UNK13TP_LSOUT1_G  TP01  [TP_040_T]  241.37 484.9 0 top
UNK13TP_LSOUT1_S  TP01  [TP_040_T]  201.65 298.48 270 top
UNK13TP_LSOUT2/SUSPEND1_G  TP01  [TP_040_T]  243.35 484.9 0 top
UNK13TP_LSOUT2/SUSPEND1_S  TP01  [TP_040_T]  201.65 295.94 0 top
UNK13TP_LSOUT2/SUSPEND_F  TP01  [TP_040_T]  218.86 244.47 180 top
UNK13TP_NCHG/ATB0_F  TP01  [TP_040_T]  203.93 292.54 0 top
UNK13TP_NCHG/ATB0_G  TP01  [TP_040_T]  203.93 288.14 0 top
UNK13TP_NCHG/ATB0_S  TP01  [TP_040_T]  207.13 290.34 0 top
UNK13TP_NPG/ATB1_F  TP01  [TP_040_T]  196.47 292.54 0 top
UNK13TP_NPG/ATB1_G  TP01  [TP_040_T]  196.47 288.14 0 top
UNK13TP_NPG/ATB1_S  TP01  [TP_040_T]  199.67 292.54 0 top
UNK13TP_NTC  TP01  [TP_040_T]  211.39 307.08 180 top
UNK13TP_REF_5V  TP01  [TP_040_T]  214.59 242.27 180 top
UNK13TP_SCL  TP01  [TP_040_T]  196.47 330.46 0 top
UNK13TP_SDA  TP01  [TP_040_T]  199.67 330.46 0 top
UNK13TP_SHPHLD_F  TP01  [TP_040_T]  199.11 298.48 270 top
UNK13TP_SHPHLD_S  TP01  [TP_040_T]  199.11 295.94 90 top
UNK13TP_SW_F  TP01  [TP_040_T]  216.07 330.46 0 top
UNK13TP_SW_S  TP01  [TP_040_T]  213.53 330.46 0 top
UNK13TP_VBAT_F  TP01  [TP_040_T]  222.06 287.14 0 top
UNK13TP_VBAT_S  TP01  [TP_040_T]  218.86 287.14 0 top
UNK13TP_VBUS_F  TP01  [TP_040_T]  203.37 330.46 0 top
UNK13TP_VBUS_S  TP01  [TP_040_T]  205.91 330.46 0 top
UNK13TP_VDDIO_F  TP01  [TP_040_T]  218.61 335.54 0 top
UNK13TP_VDDIO_S  TP01  [TP_040_T]  245.34 484.9 0 top
UNK13TP_VEST  TP01  [TP_040_T]  193.28 269.26 0 top
UNK13TP_VOUT_F  TP01  [TP_040_T]  247.32 484.9 0 top
UNK13TP_VOUT_S  TP01  [TP_040_T]  218.61 330.46 0 top
UNK13TP_VSYS_F  TP01  [TP_040_T]  205.91 335.54 0 top
UNK13TP_VSYS_S  TP01  [TP_040_T]  203.37 335.54 0 top
UNK13U1  ADR4550BRZ-SOIC8  [SO8_195X127MM]  216.83 296.98 180 bottom
UNK14C1  1U-6.3-X7R-S6-MU  [C0603]  199.36 142.49 90 bottom
UNK14C2  2.2U-25-X8R-SA-TDK  [C1206]  215.84 178.21 180 bottom
UNK14C3  10U-6.3-X7R-S6-SS  [C0603]  211.91 177.36 270 bottom
UNK14C4  2.2U-25-X8R-SA-TDK  [C1206]  208.38 192.05 180 bottom
UNK14C5  2.2U-25-X8R-SA-TDK  [C1206]  202.68 192.05 0 bottom
UNK14C6  4.7U-6.3-X-S6  [C0603]  221.21 178.21 180 bottom
UNK14C7  0.1U-25-X7R-S6-YA  [C0603]  221.75 238.65 0 bottom
UNK14C8  1U-50-X7R-S6-TY  [C0603]  221.75 237.13 0 bottom
UNK14C9  0.1U-25-X7R-S6-YA  [C0603]  211.9 237.3 270 bottom
UNK14C12  2.2U-25-X8R-SA-TDK  [C1206]  206.98 142.89 90 bottom
UNK14CS1  CNC-S4  [C0402]  202.12 211.3 180 bottom
UNK14CS4  CNC-S4  [C0402]  202.12 207.49 0 bottom
UNK14CS5  CNC-S4  [C0402]  202.12 206.22 0 bottom
UNK14CS19  CNC-S4  [C0402]  215.85 207.02 0 bottom
UNK14CS20  CNC-S4  [C0402]  215.85 208.29 0 bottom
UNK14CS21  CNC-S4  [C0402]  215.85 209.56 0 bottom
UNK14CS22  CNC-S4  [C0402]  213.19 213.05 90 bottom
UNK14CS23  CNC-S4  [C0402]  211.92 213.05 90 bottom
UNK14CS25  CNC-S4  [C0402]  208.11 213.05 90 bottom
UNK14CS26  CNC-S4  [C0402]  206.84 213.05 270 bottom
UNK14CS27  CNC-S4  [C0402]  205.57 213.05 270 bottom
UNK14CS28  CNC-S4  [C0402]  204.3 213.05 90 bottom
UNK14K1  UA2-12NJ-V2  [RL_NECUA2_12V_V2]  212.99 185.33 90 bottom
UNK14K2  UA2-12NJ-V2  [RL_NECUA2_12V_V2]  205.53 185.33 90 bottom
UNK14K3  UA2-12NJ-V2  [RL_NECUA2_12V_V2]  196.66 207.46 270 bottom
UNK14K4  UA2-12NJ-V2  [RL_NECUA2_12V_V2]  205.53 169.7 90 bottom
UNK14K5  UA2-12NJ-V2  [RL_NECUA2_12V_V2]  198.07 169.7 90 bottom
UNK14K6  UA2-12NJ-V2  [RL_NECUA2_12V_V2]  212.99 169.3 270 bottom
UNK14K7  UA2-12NJ-V2  [RL_NECUA2_12V_V2]  220.46 169.7 90 bottom
UNK14K8  UA2-12NJ-V2  [RL_NECUA2_12V_V2]  198.07 185.33 90 bottom
UNK14K9  UA2-12NJ-V2  [RL_NECUA2_12V_V2]  220.46 142.72 270 bottom
UNK14K10  UA2-12NJ-V2  [RL_NECUA2_12V_V2]  220.46 185.33 90 bottom
UNK14K11  UA2-12NJ-V2  [RL_NECUA2_12V_V2]  212.99 229.98 90 bottom
UNK14K12  UA2-12NJ-V2  [RL_NECUA2_12V_V2]  220.46 229.98 90 bottom
UNK14K13  UA2-12NJ-V2  [RL_NECUA2_12V_V2]  198.07 229.58 270 bottom
UNK14K14  UA2-12NJ-V2  [RL_NECUA2_12V_V2]  205.53 229.58 270 bottom
UNK14R1  4.7K-1-S4-WA  [R0402]  196.51 201.49 180 bottom
UNK14R2  3.01K-0.1-S4-PAN  [R0402]  201.8 166.2 90 bottom
UNK14R3  10K-0.1-S4  [R0402]  209.26 172.8 270 bottom
UNK14R7  1K-1-S4  [R0402]  221.78 149.43 0 bottom
UNK14R8  1K-1-S4  [R0402]  219.14 149.43 180 bottom
UNK14R13  0-5-S4  [R0402]  151.02 484.56 0 top
UNK14R14  0-5-S4  [R0402]  153.22 484.56 0 top
UNK14R41  24K-0.1-S4  [R0402]  224.26 166.2 90 bottom
UNK14R42  44.2K-0.1-S4-PAN  [R0402]  224.26 168.4 90 bottom
UNK14RS1  0-5-S4  [R0402]  202.12 208.76 0 bottom
UNK14RS2  NC/0-5-S4  [R0402]  209.38 213.05 270 bottom
UNK14RS3  NC/0-5-S4  [R0402]  202.12 210.03 0 bottom
UNK14RS4  0-5-S4  [R0402]  210.65 213.05 270 bottom
UNK14RS5  0-5-S4  [R0402]  210.02 214.7 0 bottom
UNK14SH2  SHORT  [DEFAULT_SHORT_SMALL]  233.97 475.82 0 top
UNK14SH7  SHORT  [DEFAULT_SHORT_SMALL]  264.82 475.82 0 top
UNK14SH9  SHORT  [DEFAULT_SHORT_SMALL]  1.2 483.17 0 top
UNK14SH14  SHORT  [DEFAULT_SHORT_SMALL]  229.56 475.82 0 top
UNK14SH16  SHORT  [DEFAULT_SHORT_SMALL]  231.77 475.82 0 top
UNK14SH20  SHORT  [DEFAULT_SHORT_SMALL]  236.17 475.82 0 top
UNK14SH29  SHORT  [DEFAULT_SHORT_SMALL]  238.38 475.82 0 top
UNK14SH30  SHORT  [DEFAULT_SHORT_SMALL]  240.58 475.82 0 top
UNK14SH32  SHORT  [DEFAULT_SHORT_SMALL]  242.78 475.82 0 top
UNK14SH33  SHORT  [DEFAULT_SHORT_SMALL]  244.99 475.82 0 top
UNK14SH34  SHORT  [DEFAULT_SHORT_SMALL]  247.19 475.82 0 top
UNK14SH35  SHORT  [DEFAULT_SHORT_SMALL]  249.39 475.82 0 top
UNK14SH36  SHORT  [DEFAULT_SHORT_SMALL]  251.6 475.82 0 top
UNK14SH37  SHORT  [DEFAULT_SHORT_SMALL]  253.8 475.82 0 top
UNK14SH38  SHORT  [DEFAULT_SHORT_SMALL]  256 475.82 0 top
UNK14SH39  SHORT  [DEFAULT_SHORT_SMALL]  258.21 475.82 0 top
UNK14SH40  SHORT  [DEFAULT_SHORT_SMALL]  260.41 475.82 0 top
UNK14SH41  SHORT  [DEFAULT_SHORT_SMALL]  262.61 475.82 0 top
UNK14TP_AVSS2/TST  TP01  [TP_040_T]  193.84 214.45 0 top
UNK14TP_GPIO0  TP01  [TP_040_T]  209.17 178.59 270 top
UNK14TP_GPIO1  TP01  [TP_040_T]  209.17 176.05 90 top
UNK14TP_GPIO2  TP01  [TP_040_T]  196.47 178.59 180 top
UNK14TP_GPIO3  TP01  [TP_040_T]  196.47 176.05 90 top
UNK14TP_GPIO4  TP01  [TP_040_T]  199.01 178.59 90 top
UNK14TP_LED0  TP01  [TP_040_T]  201.55 176.05 90 top
UNK14TP_LED1  TP01  [TP_040_T]  201.55 178.59 270 top
UNK14TP_LED2  TP01  [TP_040_T]  199.01 176.05 90 top
UNK14TP_LSIN1_F  TP01  [TP_040_T]  206.98 146.72 180 top
UNK14TP_LSIN1_G  TP01  [TP_040_T]  249.3 484.9 0 top
UNK14TP_LSIN1_S  TP01  [TP_040_T]  209.52 146.72 180 top
UNK14TP_LSIN2/NCHGEN_F  TP01  [TP_040_T]  206.98 141.64 180 top
UNK14TP_LSIN2/NCHGEN_G  TP01  [TP_040_T]  251.28 484.9 0 top
UNK14TP_LSIN2/NCHGEN_S  TP01  [TP_040_T]  209.52 141.64 180 top
UNK14TP_LSOUT1_F  TP01  [TP_040_T]  253.26 484.9 0 top
UNK14TP_LSOUT1_G  TP01  [TP_040_T]  255.24 484.9 0 top
UNK14TP_LSOUT1_S  TP01  [TP_040_T]  204.09 176.05 90 top
UNK14TP_LSOUT2/SUSPEND1_G  TP01  [TP_040_T]  257.22 484.9 0 top
UNK14TP_LSOUT2/SUSPEND1_S  TP01  [TP_040_T]  204.09 178.59 180 top
UNK14TP_LSOUT2/SUSPEND_F  TP01  [TP_040_T]  259.2 484.9 0 top
UNK14TP_NCHG/ATB0_F  TP01  [TP_040_T]  203.93 233.58 0 top
UNK14TP_NCHG/ATB0_G  TP01  [TP_040_T]  203.93 229.18 0 top
UNK14TP_NCHG/ATB0_S  TP01  [TP_040_T]  207.13 231.38 0 top
UNK14TP_NPG/ATB1_F  TP01  [TP_040_T]  196.47 233.58 0 top
UNK14TP_NPG/ATB1_G  TP01  [TP_040_T]  196.47 229.18 0 top
UNK14TP_NPG/ATB1_S  TP01  [TP_040_T]  199.67 233.58 0 top
UNK14TP_NTC  TP01  [TP_040_T]  207.13 167.9 0 top
UNK14TP_REF_5V  TP01  [TP_040_T]  261.18 484.9 0 top
UNK14TP_SCL  TP01  [TP_040_T]  222.06 144.52 180 top
UNK14TP_SDA  TP01  [TP_040_T]  218.86 144.52 180 top
UNK14TP_SHPHLD_F  TP01  [TP_040_T]  206.63 176.05 90 top
UNK14TP_SHPHLD_S  TP01  [TP_040_T]  206.63 178.59 270 top
UNK14TP_SW_F  TP01  [TP_040_T]  201.9 146.72 180 top
UNK14TP_SW_S  TP01  [TP_040_T]  204.44 146.72 180 top
UNK14TP_VBAT_F  TP01  [TP_040_T]  222.06 228.18 0 top
UNK14TP_VBAT_S  TP01  [TP_040_T]  218.86 228.18 0 top
UNK14TP_VBUS_F  TP01  [TP_040_T]  214.6 146.72 180 top
UNK14TP_VBUS_S  TP01  [TP_040_T]  212.06 146.72 180 top
UNK14TP_VDDIO_F  TP01  [TP_040_T]  199.36 141.64 180 top
UNK14TP_VDDIO_S  TP01  [TP_040_T]  196.82 141.64 180 top
UNK14TP_VEST  TP01  [TP_040_T]  193.28 209.26 0 top
UNK14TP_VOUT_F  TP01  [TP_040_T]  196.82 146.72 180 top
UNK14TP_VOUT_S  TP01  [TP_040_T]  199.36 146.72 180 top
UNK14TP_VSYS_F  TP01  [TP_040_T]  212.06 141.64 180 top
UNK14TP_VSYS_S  TP01  [TP_040_T]  214.6 141.64 180 top
UNK14U1  ADR4550BRZ-SOIC8  [SO8_195X127MM]  216.32 238.02 180 bottom
UNK15C1  1U-6.3-X7R-S6-MU  [C0603]  248.61 334.69 270 bottom
UNK15C2  2.2U-25-X8R-SA-TDK  [C1206]  239.52 237.92 90 bottom
UNK15C3  10U-6.3-X7R-S6-SS  [C0603]  237.13 238.61 270 bottom
UNK15C4  2.2U-25-X8R-SA-TDK  [C1206]  229.67 237.92 90 bottom
UNK15C5  2.2U-25-X8R-SA-TDK  [C1206]  226.47 237.92 270 bottom
UNK15C6  4.7U-6.3-X-S6  [C0603]  254.26 241.42 270 bottom
UNK15C7  0.1U-25-X7R-S6-YA  [C0603]  252.25 297.61 0 bottom
UNK15C8  1U-50-X7R-S6-TY  [C0603]  252.25 296.09 0 bottom
UNK15C9  0.1U-25-X7R-S6-YA  [C0603]  242.41 296.26 270 bottom
UNK15C12  2.2U-25-X8R-SA-TDK  [C1206]  240.99 334.29 270 bottom
UNK15CS1  CNC-S4  [C0402]  232.12 271.3 180 bottom
UNK15CS4  CNC-S4  [C0402]  232.12 267.49 0 bottom
UNK15CS5  CNC-S4  [C0402]  232.12 266.22 0 bottom
UNK15CS19  CNC-S4  [C0402]  245.85 267.02 0 bottom
UNK15CS20  CNC-S4  [C0402]  245.85 268.29 0 bottom
UNK15CS21  CNC-S4  [C0402]  245.85 269.56 0 bottom
UNK15CS22  CNC-S4  [C0402]  243.19 273.05 90 bottom
UNK15CS23  CNC-S4  [C0402]  241.92 273.05 90 bottom
UNK15CS25  CNC-S4  [C0402]  238.11 273.05 90 bottom
UNK15CS26  CNC-S4  [C0402]  236.84 273.05 270 bottom
UNK15CS27  CNC-S4  [C0402]  235.57 273.05 270 bottom
UNK15CS28  CNC-S4  [C0402]  234.3 273.05 90 bottom
UNK15K1  UA2-12NJ-V2  [RL_NECUA2_12V_V2]  242.99 246.27 90 bottom
UNK15K2  UA2-12NJ-V2  [RL_NECUA2_12V_V2]  235.53 246.27 90 bottom
UNK15K3  UA2-12NJ-V2  [RL_NECUA2_12V_V2]  226.66 267.46 270 bottom
UNK15K4  UA2-12NJ-V2  [RL_NECUA2_12V_V2]  242.99 305.28 270 bottom
UNK15K5  UA2-12NJ-V2  [RL_NECUA2_12V_V2]  250.46 305.28 270 bottom
UNK15K6  UA2-12NJ-V2  [RL_NECUA2_12V_V2]  235.53 305.68 90 bottom
UNK15K7  UA2-12NJ-V2  [RL_NECUA2_12V_V2]  228.07 305.28 270 bottom
UNK15K8  UA2-12NJ-V2  [RL_NECUA2_12V_V2]  228.07 246.27 90 bottom
UNK15K9  UA2-12NJ-V2  [RL_NECUA2_12V_V2]  228.07 332.26 90 bottom
UNK15K10  UA2-12NJ-V2  [RL_NECUA2_12V_V2]  242.99 288.94 90 bottom
UNK15K11  UA2-12NJ-V2  [RL_NECUA2_12V_V2]  250.46 246.27 90 bottom
UNK15K12  UA2-12NJ-V2  [RL_NECUA2_12V_V2]  250.46 288.94 90 bottom
UNK15K13  UA2-12NJ-V2  [RL_NECUA2_12V_V2]  228.07 288.54 270 bottom
UNK15K14  UA2-12NJ-V2  [RL_NECUA2_12V_V2]  235.53 288.54 270 bottom
UNK15R1  4.7K-1-S4-WA  [R0402]  226.51 261.49 180 bottom
UNK15R2  3.01K-0.1-S4-PAN  [R0402]  246.73 308.78 270 bottom
UNK15R3  10K-0.1-S4  [R0402]  239.26 301.18 270 bottom
UNK15R7  1K-1-S4  [R0402]  226.75 325.55 180 bottom
UNK15R8  1K-1-S4  [R0402]  229.39 325.55 0 bottom
UNK15R13  0-5-S4  [R0402]  155.43 484.56 0 top
UNK15R14  0-5-S4  [R0402]  157.63 484.56 0 top
UNK15R41  24K-0.1-S4  [R0402]  224.26 308.78 270 bottom
UNK15R42  44.2K-0.1-S4-PAN  [R0402]  224.26 306.58 270 bottom
UNK15RS1  0-5-S4  [R0402]  232.12 268.76 0 bottom
UNK15RS2  NC/0-5-S4  [R0402]  239.38 273.05 270 bottom
UNK15RS3  NC/0-5-S4  [R0402]  232.12 270.03 0 bottom
UNK15RS4  0-5-S4  [R0402]  240.65 273.05 270 bottom
UNK15RS5  0-5-S4  [R0402]  240.02 274.7 0 bottom
UNK15SH2  SHORT  [DEFAULT_SHORT_SMALL]  7.81 483.17 0 top
UNK15SH7  SHORT  [DEFAULT_SHORT_SMALL]  38.66 483.17 0 top
UNK15SH9  SHORT  [DEFAULT_SHORT_SMALL]  40.86 483.17 0 top
UNK15SH14  SHORT  [DEFAULT_SHORT_SMALL]  3.41 483.17 0 top
UNK15SH16  SHORT  [DEFAULT_SHORT_SMALL]  5.61 483.17 0 top
UNK15SH20  SHORT  [DEFAULT_SHORT_SMALL]  10.02 483.17 0 top
UNK15SH29  SHORT  [DEFAULT_SHORT_SMALL]  12.22 483.17 0 top
UNK15SH30  SHORT  [DEFAULT_SHORT_SMALL]  14.42 483.17 0 top
UNK15SH32  SHORT  [DEFAULT_SHORT_SMALL]  16.63 483.17 0 top
UNK15SH33  SHORT  [DEFAULT_SHORT_SMALL]  18.83 483.17 0 top
UNK15SH34  SHORT  [DEFAULT_SHORT_SMALL]  21.03 483.17 0 top
UNK15SH35  SHORT  [DEFAULT_SHORT_SMALL]  23.24 483.17 0 top
UNK15SH36  SHORT  [DEFAULT_SHORT_SMALL]  25.44 483.17 0 top
UNK15SH37  SHORT  [DEFAULT_SHORT_SMALL]  27.64 483.17 0 top
UNK15SH38  SHORT  [DEFAULT_SHORT_SMALL]  29.84 483.17 0 top
UNK15SH39  SHORT  [DEFAULT_SHORT_SMALL]  32.05 483.17 0 top
UNK15SH40  SHORT  [DEFAULT_SHORT_SMALL]  34.25 483.17 0 top
UNK15SH41  SHORT  [DEFAULT_SHORT_SMALL]  36.45 483.17 0 top
UNK15TP_AVSS2/TST  TP01  [TP_040_T]  223.84 274.45 0 top
UNK15TP_GPIO0  TP01  [TP_040_T]  226.57 295.94 90 top
UNK15TP_GPIO1  TP01  [TP_040_T]  226.57 298.48 270 top
UNK15TP_GPIO2  TP01  [TP_040_T]  239.27 295.94 0 top
UNK15TP_GPIO3  TP01  [TP_040_T]  239.27 298.48 270 top
UNK15TP_GPIO4  TP01  [TP_040_T]  236.73 295.94 270 top
UNK15TP_LED0  TP01  [TP_040_T]  234.19 298.48 270 top
UNK15TP_LED1  TP01  [TP_040_T]  234.19 295.94 90 top
UNK15TP_LED2  TP01  [TP_040_T]  236.73 298.48 270 top
UNK15TP_LSIN1_F  TP01  [TP_040_T]  240.99 330.46 0 top
UNK15TP_LSIN1_G  TP01  [TP_040_T]  263.17 484.9 0 top
UNK15TP_LSIN1_S  TP01  [TP_040_T]  238.45 330.46 0 top
UNK15TP_LSIN2/NCHGEN_F  TP01  [TP_040_T]  240.99 335.54 0 top
UNK15TP_LSIN2/NCHGEN_G  TP01  [TP_040_T]  265.15 484.9 0 top
UNK15TP_LSIN2/NCHGEN_S  TP01  [TP_040_T]  238.45 335.54 0 top
UNK15TP_LSOUT1_F  TP01  [TP_040_T]  229.67 244.47 180 top
UNK15TP_LSOUT1_G  TP01  [TP_040_T]  1.09 486.88 0 top
UNK15TP_LSOUT1_S  TP01  [TP_040_T]  231.65 298.48 270 top
UNK15TP_LSOUT2/SUSPEND1_G  TP01  [TP_040_T]  3.07 486.88 0 top
UNK15TP_LSOUT2/SUSPEND1_S  TP01  [TP_040_T]  231.65 295.94 0 top
UNK15TP_LSOUT2/SUSPEND_F  TP01  [TP_040_T]  248.86 244.47 180 top
UNK15TP_NCHG/ATB0_F  TP01  [TP_040_T]  233.93 292.54 0 top
UNK15TP_NCHG/ATB0_G  TP01  [TP_040_T]  233.93 288.14 0 top
UNK15TP_NCHG/ATB0_S  TP01  [TP_040_T]  237.13 290.34 0 top
UNK15TP_NPG/ATB1_F  TP01  [TP_040_T]  226.47 292.54 0 top
UNK15TP_NPG/ATB1_G  TP01  [TP_040_T]  226.47 288.14 0 top
UNK15TP_NPG/ATB1_S  TP01  [TP_040_T]  229.67 292.54 0 top
UNK15TP_NTC  TP01  [TP_040_T]  241.39 307.08 180 top
UNK15TP_REF_5V  TP01  [TP_040_T]  244.59 242.27 180 top
UNK15TP_SCL  TP01  [TP_040_T]  226.47 330.46 0 top
UNK15TP_SDA  TP01  [TP_040_T]  229.67 330.46 0 top
UNK15TP_SHPHLD_F  TP01  [TP_040_T]  229.11 298.48 270 top
UNK15TP_SHPHLD_S  TP01  [TP_040_T]  229.11 295.94 90 top
UNK15TP_SW_F  TP01  [TP_040_T]  246.07 330.46 0 top
UNK15TP_SW_S  TP01  [TP_040_T]  243.53 330.46 0 top
UNK15TP_VBAT_F  TP01  [TP_040_T]  252.06 287.14 0 top
UNK15TP_VBAT_S  TP01  [TP_040_T]  248.86 287.14 0 top
UNK15TP_VBUS_F  TP01  [TP_040_T]  233.37 330.46 0 top
UNK15TP_VBUS_S  TP01  [TP_040_T]  235.91 330.46 0 top
UNK15TP_VDDIO_F  TP01  [TP_040_T]  248.61 335.54 0 top
UNK15TP_VDDIO_S  TP01  [TP_040_T]  5.05 486.88 0 top
UNK15TP_VEST  TP01  [TP_040_T]  223.28 269.26 0 top
UNK15TP_VOUT_F  TP01  [TP_040_T]  7.04 486.88 0 top
UNK15TP_VOUT_S  TP01  [TP_040_T]  248.61 330.46 0 top
UNK15TP_VSYS_F  TP01  [TP_040_T]  235.91 335.54 0 top
UNK15TP_VSYS_S  TP01  [TP_040_T]  233.37 335.54 0 top
UNK15U1  ADR4550BRZ-SOIC8  [SO8_195X127MM]  246.83 296.98 180 bottom
UNK16C1  1U-6.3-X7R-S6-MU  [C0603]  229.36 142.49 90 bottom
UNK16C2  2.2U-25-X8R-SA-TDK  [C1206]  245.84 178.21 180 bottom
UNK16C3  10U-6.3-X7R-S6-SS  [C0603]  241.91 177.36 270 bottom
UNK16C4  2.2U-25-X8R-SA-TDK  [C1206]  238.38 192.05 180 bottom
UNK16C5  2.2U-25-X8R-SA-TDK  [C1206]  232.68 192.05 0 bottom
UNK16C6  4.7U-6.3-X-S6  [C0603]  251.21 178.21 180 bottom
UNK16C7  0.1U-25-X7R-S6-YA  [C0603]  251.74 238.65 0 bottom
UNK16C8  1U-50-X7R-S6-TY  [C0603]  251.74 237.13 0 bottom
UNK16C9  0.1U-25-X7R-S6-YA  [C0603]  241.9 237.3 270 bottom
UNK16C12  2.2U-25-X8R-SA-TDK  [C1206]  236.98 142.89 90 bottom
UNK16CS1  CNC-S4  [C0402]  232.12 211.3 180 bottom
UNK16CS4  CNC-S4  [C0402]  232.12 207.49 0 bottom
UNK16CS5  CNC-S4  [C0402]  232.12 206.22 0 bottom
UNK16CS19  CNC-S4  [C0402]  245.85 207.02 0 bottom
UNK16CS20  CNC-S4  [C0402]  245.85 208.29 0 bottom
UNK16CS21  CNC-S4  [C0402]  245.85 209.56 0 bottom
UNK16CS22  CNC-S4  [C0402]  243.19 213.05 90 bottom
UNK16CS23  CNC-S4  [C0402]  241.92 213.05 90 bottom
UNK16CS25  CNC-S4  [C0402]  238.11 213.05 90 bottom
UNK16CS26  CNC-S4  [C0402]  236.84 213.05 270 bottom
UNK16CS27  CNC-S4  [C0402]  235.57 213.05 270 bottom
UNK16CS28  CNC-S4  [C0402]  234.3 213.05 90 bottom
UNK16K1  UA2-12NJ-V2  [RL_NECUA2_12V_V2]  242.99 185.33 90 bottom
UNK16K2  UA2-12NJ-V2  [RL_NECUA2_12V_V2]  235.53 185.33 90 bottom
UNK16K3  UA2-12NJ-V2  [RL_NECUA2_12V_V2]  226.66 207.46 270 bottom
UNK16K4  UA2-12NJ-V2  [RL_NECUA2_12V_V2]  235.53 169.7 90 bottom
UNK16K5  UA2-12NJ-V2  [RL_NECUA2_12V_V2]  228.07 169.7 90 bottom
UNK16K6  UA2-12NJ-V2  [RL_NECUA2_12V_V2]  242.99 169.3 270 bottom
UNK16K7  UA2-12NJ-V2  [RL_NECUA2_12V_V2]  250.46 169.7 90 bottom
UNK16K8  UA2-12NJ-V2  [RL_NECUA2_12V_V2]  228.07 185.33 90 bottom
UNK16K9  UA2-12NJ-V2  [RL_NECUA2_12V_V2]  250.46 142.72 270 bottom
UNK16K10  UA2-12NJ-V2  [RL_NECUA2_12V_V2]  250.46 185.33 90 bottom
UNK16K11  UA2-12NJ-V2  [RL_NECUA2_12V_V2]  242.99 229.98 90 bottom
UNK16K12  UA2-12NJ-V2  [RL_NECUA2_12V_V2]  250.46 229.98 90 bottom
UNK16K13  UA2-12NJ-V2  [RL_NECUA2_12V_V2]  228.07 229.58 270 bottom
UNK16K14  UA2-12NJ-V2  [RL_NECUA2_12V_V2]  235.53 229.58 270 bottom
UNK16R1  4.7K-1-S4-WA  [R0402]  226.51 201.49 180 bottom
UNK16R2  3.01K-0.1-S4-PAN  [R0402]  231.8 166.2 90 bottom
UNK16R3  10K-0.1-S4  [R0402]  239.26 172.8 270 bottom
UNK16R7  1K-1-S4  [R0402]  251.78 149.43 0 bottom
UNK16R8  1K-1-S4  [R0402]  249.14 149.43 180 bottom
UNK16R13  0-5-S4  [R0402]  159.83 484.56 0 top
UNK16R14  0-5-S4  [R0402]  162.04 484.56 0 top
UNK16R41  24K-0.1-S4  [R0402]  254.26 166.2 90 bottom
UNK16R42  44.2K-0.1-S4-PAN  [R0402]  254.26 168.4 90 bottom
UNK16RS1  0-5-S4  [R0402]  232.12 208.76 0 bottom
UNK16RS2  NC/0-5-S4  [R0402]  239.38 213.05 270 bottom
UNK16RS3  NC/0-5-S4  [R0402]  232.12 210.03 0 bottom
UNK16RS4  0-5-S4  [R0402]  240.65 213.05 270 bottom
UNK16RS5  0-5-S4  [R0402]  240.02 214.7 0 bottom
UNK16SH2  SHORT  [DEFAULT_SHORT_SMALL]  47.47 483.17 0 top
UNK16SH7  SHORT  [DEFAULT_SHORT_SMALL]  78.32 483.17 0 top
UNK16SH9  SHORT  [DEFAULT_SHORT_SMALL]  80.52 483.17 0 top
UNK16SH14  SHORT  [DEFAULT_SHORT_SMALL]  43.06 483.17 0 top
UNK16SH16  SHORT  [DEFAULT_SHORT_SMALL]  45.27 483.17 0 top
UNK16SH20  SHORT  [DEFAULT_SHORT_SMALL]  49.67 483.17 0 top
UNK16SH29  SHORT  [DEFAULT_SHORT_SMALL]  51.88 483.17 0 top
UNK16SH30  SHORT  [DEFAULT_SHORT_SMALL]  54.08 483.17 0 top
UNK16SH32  SHORT  [DEFAULT_SHORT_SMALL]  56.28 483.17 0 top
UNK16SH33  SHORT  [DEFAULT_SHORT_SMALL]  58.49 483.17 0 top
UNK16SH34  SHORT  [DEFAULT_SHORT_SMALL]  60.69 483.17 0 top
UNK16SH35  SHORT  [DEFAULT_SHORT_SMALL]  62.89 483.17 0 top
UNK16SH36  SHORT  [DEFAULT_SHORT_SMALL]  65.1 483.17 0 top
UNK16SH37  SHORT  [DEFAULT_SHORT_SMALL]  67.3 483.17 0 top
UNK16SH38  SHORT  [DEFAULT_SHORT_SMALL]  69.5 483.17 0 top
UNK16SH39  SHORT  [DEFAULT_SHORT_SMALL]  71.71 483.17 0 top
UNK16SH40  SHORT  [DEFAULT_SHORT_SMALL]  73.91 483.17 0 top
UNK16SH41  SHORT  [DEFAULT_SHORT_SMALL]  76.11 483.17 0 top
UNK16TP_AVSS2/TST  TP01  [TP_040_T]  223.84 214.45 0 top
UNK16TP_GPIO0  TP01  [TP_040_T]  239.17 178.59 270 top
UNK16TP_GPIO1  TP01  [TP_040_T]  239.17 176.05 90 top
UNK16TP_GPIO2  TP01  [TP_040_T]  226.47 178.59 180 top
UNK16TP_GPIO3  TP01  [TP_040_T]  226.47 176.05 90 top
UNK16TP_GPIO4  TP01  [TP_040_T]  229.01 178.59 90 top
UNK16TP_LED0  TP01  [TP_040_T]  231.55 176.05 90 top
UNK16TP_LED1  TP01  [TP_040_T]  231.55 178.59 270 top
UNK16TP_LED2  TP01  [TP_040_T]  229.01 176.05 90 top
UNK16TP_LSIN1_F  TP01  [TP_040_T]  236.98 146.72 180 top
UNK16TP_LSIN1_G  TP01  [TP_040_T]  9.02 486.88 0 top
UNK16TP_LSIN1_S  TP01  [TP_040_T]  239.52 146.72 180 top
UNK16TP_LSIN2/NCHGEN_F  TP01  [TP_040_T]  236.98 141.64 180 top
UNK16TP_LSIN2/NCHGEN_G  TP01  [TP_040_T]  11 486.88 0 top
UNK16TP_LSIN2/NCHGEN_S  TP01  [TP_040_T]  239.52 141.64 180 top
UNK16TP_LSOUT1_F  TP01  [TP_040_T]  12.98 486.88 0 top
UNK16TP_LSOUT1_G  TP01  [TP_040_T]  14.96 486.88 0 top
UNK16TP_LSOUT1_S  TP01  [TP_040_T]  234.09 176.05 90 top
UNK16TP_LSOUT2/SUSPEND1_G  TP01  [TP_040_T]  16.94 486.88 0 top
UNK16TP_LSOUT2/SUSPEND1_S  TP01  [TP_040_T]  234.09 178.59 180 top
UNK16TP_LSOUT2/SUSPEND_F  TP01  [TP_040_T]  18.92 486.88 0 top
UNK16TP_NCHG/ATB0_F  TP01  [TP_040_T]  233.93 233.58 0 top
UNK16TP_NCHG/ATB0_G  TP01  [TP_040_T]  233.93 229.18 0 top
UNK16TP_NCHG/ATB0_S  TP01  [TP_040_T]  237.13 231.38 0 top
UNK16TP_NPG/ATB1_F  TP01  [TP_040_T]  226.47 233.58 0 top
UNK16TP_NPG/ATB1_G  TP01  [TP_040_T]  226.47 229.18 0 top
UNK16TP_NPG/ATB1_S  TP01  [TP_040_T]  229.67 233.58 0 top
UNK16TP_NTC  TP01  [TP_040_T]  237.13 167.9 0 top
UNK16TP_REF_5V  TP01  [TP_040_T]  20.9 486.88 0 top
UNK16TP_SCL  TP01  [TP_040_T]  252.06 144.52 180 top
UNK16TP_SDA  TP01  [TP_040_T]  248.86 144.52 180 top
UNK16TP_SHPHLD_F  TP01  [TP_040_T]  236.63 176.05 90 top
UNK16TP_SHPHLD_S  TP01  [TP_040_T]  236.63 178.59 270 top
UNK16TP_SW_F  TP01  [TP_040_T]  231.9 146.72 180 top
UNK16TP_SW_S  TP01  [TP_040_T]  234.44 146.72 180 top
UNK16TP_VBAT_F  TP01  [TP_040_T]  252.06 228.18 0 top
UNK16TP_VBAT_S  TP01  [TP_040_T]  248.86 228.18 0 top
UNK16TP_VBUS_F  TP01  [TP_040_T]  244.6 146.72 180 top
UNK16TP_VBUS_S  TP01  [TP_040_T]  242.06 146.72 180 top
UNK16TP_VDDIO_F  TP01  [TP_040_T]  229.36 141.64 180 top
UNK16TP_VDDIO_S  TP01  [TP_040_T]  226.82 141.64 180 top
UNK16TP_VEST  TP01  [TP_040_T]  223.28 209.26 0 top
UNK16TP_VOUT_F  TP01  [TP_040_T]  226.82 146.72 180 top
UNK16TP_VOUT_S  TP01  [TP_040_T]  229.36 146.72 180 top
UNK16TP_VSYS_F  TP01  [TP_040_T]  242.06 141.64 180 top
UNK16TP_VSYS_S  TP01  [TP_040_T]  244.6 141.64 180 top
UNK16U1  ADR4550BRZ-SOIC8  [SO8_195X127MM]  246.32 238.02 180 bottom
UNK038NC-GRIFFI18R-A100  REF-CODE-PCB  [PCB_CODE]  196.48 484.41 0 top
UNK730-03146-001_FP-ATE  REF-CODE-SOCKET  [SOCKET_CODE]  129.17 486.39 0 top
UNK980NC-GRIFFI-1C4  REF-CODE-PCB  [PCB_CODE]  96.85 472.67 0 top
UNK*  TP01  [unnamed#2]  252.06 230.38 0 top
UNK*#2  TP01  [unnamed#2]  252.06 225.98 0 top
USER_5V1  LDG-2-S8  [LED_0805]  71.76 111.83 90 top
USER_12V1  LDG-2-S8  [LED_0805]  17.15 126.05 90 top
USER_-5V1  LDG-2-S8  [LED_0805]  82.68 110.3 90 top

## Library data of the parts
